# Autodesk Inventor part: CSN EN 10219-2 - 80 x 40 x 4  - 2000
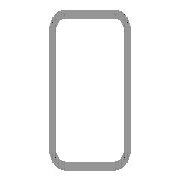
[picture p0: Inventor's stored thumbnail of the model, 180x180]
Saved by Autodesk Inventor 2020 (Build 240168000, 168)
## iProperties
Created: 2019-01
Part Number: CSN EN 10219-2 - 80 x 40 x 4  - 2000
Material: Ocel
Description: Duté svařované profily tvářené za studena z nelegované a jemnozrnné konstrukční oceli
Document SubType Name: Modeling
Standard: CSN EN 10219-2
Designer: doma
Standards Organization: CSN
Language: cs-CZ
Size Designation: 80 x 40 x 4  - 2000
Categories: <MemberInstance><Categories><Category DisplayName="Konstrukční profily" InternalName="089c4875-fa83-4c05-b084-43b9cc11f5ed" Mnemonic="GRDR"><CategoryParameter D
Stock Number: 80 x 40 x 4
Density: 7.85 g/cm^3
Appearance: Plech
Mass: 2570.91 g
Surface Area: 1656.03 cm^2
Volume: 327.504 cm^3
IsCustomPart: 1
G_L: 2000,000 mm
Author: doma
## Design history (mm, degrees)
node "Počáteční rovina"
node "Koncová rovina"
sketch "Náčrt"
  geometry: L1 (-20, -32)-(-20, 32); L2 (-12, 40)-(12, 40); L3 (20, 32)-(20, -32); L4 (12, -40)-(-12, -40); L5 (-12, 36)-(12, 36); L6 (16, 32)-(16, -32); L7 (12, -36)-(-12, -36); L8 (-16, -32)-(-16, 32); L9 (0, 58.32)-(0, -58.32) reference; L10 (-30.32, 0)-(30.32, 0) reference; A1 r 8 centre (-12, -32) between (-20, -32) and (-12, -40); A2 r 8 centre (-12, 32) between (-12, 40) and (-20, 32); A3 r 8 centre (12, 32) between (20, 32) and (12, 40); A4 r 8 centre (12, -32) between (12, -40) and (20, -32); A5 r 4 centre (-12, 32) between (-12, 36) and (-16, 32); A6 r 4 centre (12, 32) between (16, 32) and (12, 36); A7 r 4 centre (12, -32) between (12, -36) and (16, -32); A8 r 4 centre (-12, -32) between (-16, -32) and (-12, -36)
  constraints: 16 end point, 16 point on circle, 8 centre point, 8 tangent, 4 parallel, 3 equal radius, 2 perpendicular, 7 other
  dimensions: "d7" = 8 radius of A1 (= G_IR); "d10" = 80 distance between parallel lines of L2 L4 (= G_H); "d11" = 40 distance between parallel lines of L1 L3 (= G_W); "d12" = 4 distance between parallel lines of L3 L6 (= G_T); "d15" = 40 distance between parallel lines of L2 L10 (= 0.5 x d10); "d16" = 20 distance between parallel lines of L9 L3 (= 0.5 x d11)
extrude "Těleso" new body sketch "Náčrt" stored distance "d3" = 2000 (= G_L); taper "d4" = 0 deg
node "Driven Length"
  sketch "Sketch3"
    geometry: L1 (0, 0)-(10, 0) reference
    constraints: 2 end point, 1 horizontal
  workplane "Work Plane3"
  sketch "Sketch4"
    geometry: L1 (-2, 0)-(12, 0) reference; L2 (-2, 2000)-(12, 2000) reference
    dimensions: "d18" = 2000 distance between parallel lines of L1 L2 (derived)
sketch "Náčrt5"
  geometry: L1 (753.137, 72)-(830, -4.863) reference; L2 (830, 72)-(830, -928) reference; L3 (720, -8)-(750, -38) reference; L4 (750, 72)-(750, -928) reference; L5 (2000, -8)-(0, -8) reference; L6 (720, -8)-(753.137, 72); L7 (2000, 72)-(0, 72) reference; L8 (340, -288)-(340, -38) reference; L9 (340, -38)-(340, -8); L10 (340, -288)-(750, -288); L11 (545, -288)-(545, -32.155); L12 (370, -8)-(336.863, 72); L13 (336.863, 72)-(138.824, 154.03); L14 (138.824, 154.03)-(-68.358, 82.341); L15 (-68.358, 82.341)-(3.482, -125.277); L16 (3.482, -125.277)-(370, -8); L17 (720, -8)-(926.312, -271.224); L18 (926.312, -271.224)-(1059.334, -54.831); L19 (903.006, 144.622)-(753.137, 72); L20 (903.006, 144.622)-(2093.919, 198.879); L21 (2093.919, 198.879)-(2184.292, -163.028); L22 (2184.292, -163.028)-(1059.334, -54.831); 1 further point
  constraints: 30 end point, 6 point on line, 4 perpendicular, 2 symmetric about line, 1 midpoint
extrude "Vysunutí2" cut sketch "Náčrt5" extent not by distance; stored distance "d19" = 0; taper "d20" = 0 deg
chamfer "Zkosení1" distance "d21" = 2; stored, may be unused: second distance "d22" = 2, angle "d23" = 45 deg
body "Solid1"
node "Referenční1"
node "Referenční2"
node "Referenční3"
node "Referenční4"
node "Referenční5"
other parameters: "G_W" = 40 [user parameter; used in 1 equation term], "G_H" = 80 [user parameter; used in 1 equation term], "G_T" = 4 [user parameter; used in 1 equation term], "G_IR" = 8 [user parameter; used in 1 equation term], "G_L" = 2000 (= d18) [user parameter; used in 1 equation term], "G_OFFSET_START" = 0 [user parameter; used in 1 equation term], "G_OFFSET_END" = 0 [user parameter; used in 1 equation term], "d13" = 0 (computed from G_OFFSET_START), "d17" = 90 deg
